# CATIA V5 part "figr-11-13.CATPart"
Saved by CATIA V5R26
Part number: Part1
Bounding box of the stored display mesh (mm): x -10 to 5, y -10.258 to 7.91, z -1.915 to 2.054
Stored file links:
  D:\_Deepak\CATIA\CATIA V5-6R2016_Deepak\Resources\Part files\Partfiles\c11_catia_v5_6r2016_prt\figr-11-13.CATPart
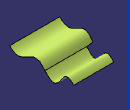
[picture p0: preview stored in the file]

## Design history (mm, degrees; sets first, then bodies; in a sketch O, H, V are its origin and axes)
Set1
  Sketch1 on yz-plane, origin (0, 0, 0), H (0, 1, 0), V (0, 0, 1)
    spline S1 through (-0.358, 0) (-3.1664, 2.0538) (-6.7822, 0.4079) (-10.2576, 1.6423)
    point P1 (-0.358, 0)
    coincidence: P1 H
  Extrude1: Element1 Sketch1, Lim1 5, Lim2 10, Direction yz-plane
  Sketch2 on yz-plane, origin (0, 0, 0), H (0, 1, 0), V (0, 0, 1)
    spline S1 through (0, 0) (3.5471, -1.4404) (5.7957, 1.2855) (7.9098, 0)
    point P1 (0, 0)
    point P2 (7.9098, 0)
    coincidence: P1 O, P2 H
  Extrude2: Element1 Sketch2, Lim1 4, Lim2 8, Direction yz-plane
  Healing1: BodyToHeal (Extrude2; Extrude1), TangencyAngle 0.5, SharpnessAngle 0.5
Body1 (main body)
